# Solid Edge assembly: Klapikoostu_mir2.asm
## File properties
Author: Türk
Template: Iso Assembly.asm
Last saved by: Türk
Revision: 3
Application: Solid Edge
Username: Türk
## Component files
Klapi vedru_mir.par
Klapipuks.par
Klapp.par
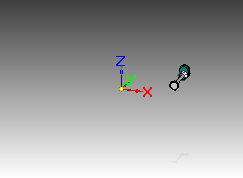
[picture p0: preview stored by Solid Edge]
